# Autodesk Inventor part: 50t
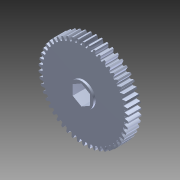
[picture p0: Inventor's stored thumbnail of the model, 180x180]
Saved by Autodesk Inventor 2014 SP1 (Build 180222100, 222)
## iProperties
Created: 2014-11
Part Number: 50t
Material: Aluminum 6061
Document SubType Name: Modeling
Designer: Michael
Density: 2.71 g/cm^3
Appearance: Aluminum - Flat
Title: 217-3572-STEP.STEP
Description: STEP AP214
Creation Date: 2013-12-09
Sending System: SolidWorks 2013
Preprocessor: SwSTEP 2.0
Author: Michael
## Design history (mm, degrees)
node "50t1"
node "Combine1"
node "Base1"
